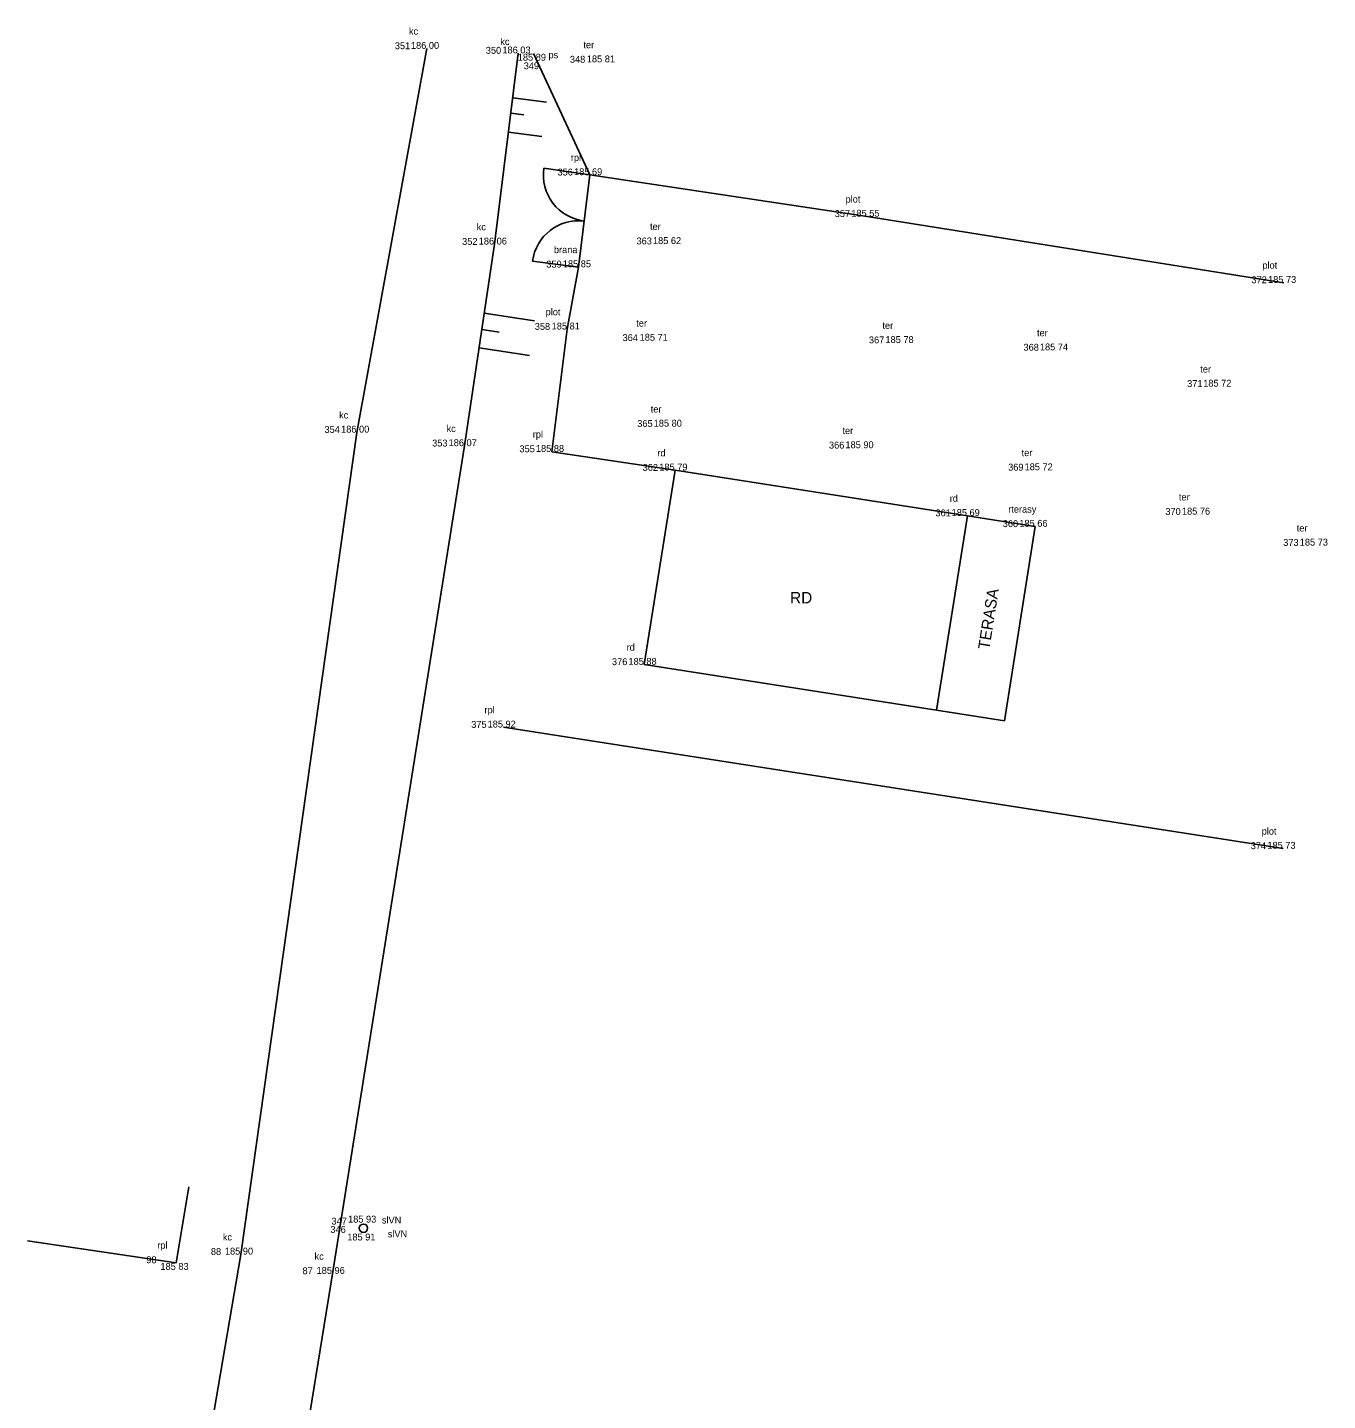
# Model space of a CAD drawing. Extents: x -598527 to -598215, y -1172822 to -1172560.
# Drawn here: x -598511.2 to -598454.6, y -1172660 to -1172600.2 of the extents above; entities that cross this region are included whole.
import ezdxf

# ---------------------------------------------------------------- set-up
doc = ezdxf.new("R2010")
doc.units = 0
for name, color, linetype in [('Body', 7, 'Continuous'), ('Body čísla', 7, 'Continuous'), ('Budovy', 7, 'Continuous'), ('Kody', 7, 'Continuous'), ('PATTERN_CLASS', 7, 'Continuous'), ('Ploty', 7, 'Continuous'), ('Popisy objektu', 7, 'Continuous'), ('Výšky', 7, 'Continuous')]:
    doc.layers.add(name, color=color, linetype=linetype)

msp = doc.modelspace()

# ---------------------------------------------------------------- linework, layer by layer
at = {"layer": 'Body'}
for p, q in [((-598493.82, -1172601.11), (-598493.82, -1172601.11)), ((-598489.84, -1172601.31), (-598489.84, -1172601.31)), ((-598489.17, -1172601.32), (-598489.17, -1172601.32)), ((-598486.18, -1172601.7), (-598486.18, -1172601.7)), ((-598486.72, -1172606.61), (-598486.72, -1172606.61)), ((-598474.65, -1172608.42), (-598474.65, -1172608.42)), ((-598490.87, -1172609.63), (-598490.87, -1172609.63)), ((-598483.28, -1172609.61), (-598483.28, -1172609.61)), ((-598487.21, -1172610.62), (-598487.21, -1172610.62)), ((-598456.5, -1172611.3), (-598456.5, -1172611.3)), ((-598487.71, -1172613.33), (-598487.71, -1172613.33)), ((-598483.88, -1172613.82), (-598483.88, -1172613.82)), ((-598473.16, -1172613.92), (-598473.16, -1172613.92)), ((-598466.43, -1172614.24), (-598466.43, -1172614.24)), ((-598459.32, -1172615.82), (-598459.32, -1172615.82)), ((-598483.25, -1172617.56), (-598483.25, -1172617.56)), ((-598496.86, -1172617.82), (-598496.86, -1172617.82)), ((-598492.18, -1172618.41), (-598492.18, -1172618.41)), ((-598488.38, -1172618.66), (-598488.38, -1172618.66)), ((-598474.9, -1172618.5), (-598474.9, -1172618.5)), ((-598483.01, -1172619.47), (-598483.01, -1172619.47)), ((-598467.1, -1172619.46), (-598467.1, -1172619.46)), ((-598470.28, -1172621.45), (-598470.28, -1172621.45)), ((-598460.25, -1172621.39), (-598460.25, -1172621.39)), ((-598467.33, -1172621.92), (-598467.33, -1172621.92)), ((-598455.12, -1172622.74), (-598455.12, -1172622.74)), ((-598484.35, -1172627.93), (-598484.35, -1172627.93)), ((-598490.48, -1172630.66), (-598490.48, -1172630.66)), ((-598456.53, -1172635.94), (-598456.53, -1172635.94)), ((-598496.61, -1172652.65), (-598496.61, -1172652.65)), ((-598496.56, -1172652.29), (-598496.56, -1172652.29)), ((-598504.73, -1172653.97), (-598504.73, -1172653.97)), ((-598501.92, -1172653.61), (-598501.92, -1172653.61)), ((-598497.93, -1172654.45), (-598497.93, -1172654.45))]:
    msp.add_line(p, q, dxfattribs=at)
at = {"layer": 'Budovy'}
for p, q in [((-598471.62, -1172629.91), (-598470.28, -1172621.45)), ((-598470.28, -1172621.45), (-598467.33, -1172621.92)), ((-598468.67, -1172630.38), (-598467.33, -1172621.92)), ((-598471.62, -1172629.91), (-598468.67, -1172630.38))]:
    msp.add_line(p, q, dxfattribs=at)
for points in [[(-598470.28, -1172621.45), (-598483.01, -1172619.47), (-598484.35, -1172627.93)], [(-598471.62, -1172629.91), (-598484.35, -1172627.93)]]:
    msp.add_lwpolyline(points, dxfattribs=at)
at = {"layer": 'PATTERN_CLASS'}
for p, q in [((-598489.17, -1172601.32), (-598486.72, -1172606.61)), ((-598490.08, -1172603.251), (-598488.601, -1172603.435)), ((-598490.163, -1172603.915), (-598489.594, -1172603.986)), ((-598490.266, -1172604.753), (-598488.808, -1172604.933)), ((-598491.318, -1172612.634), (-598489.135, -1172612.96)), ((-598491.424, -1172613.343), (-598490.663, -1172613.457)), ((-598491.543, -1172614.137), (-598489.348, -1172614.465))]:
    msp.add_line(p, q, dxfattribs=at)
for points in [[(-598493.82, -1172601.11), (-598496.86, -1172617.82), (-598501.92, -1172653.61), (-598505.54, -1172674.85)], [(-598492.58, -1172680.02), (-598497.74, -1172678.52), (-598500.61, -1172676.78), (-598500.8, -1172674.68), (-598499.89, -1172667.42), (-598499.27, -1172662.77), (-598497.93, -1172654.45), (-598492.18, -1172618.41), (-598490.87, -1172609.63), (-598489.84, -1172601.31)]]:
    msp.add_lwpolyline(points, dxfattribs=at)
msp.add_circle((-598496.579, -1172652.471), 0.182, dxfattribs=at)
at = {"layer": 'Ploty'}
for p, q in [((-598486.72, -1172606.61), (-598488.719, -1172606.319)), ((-598487.21, -1172610.62), (-598489.214, -1172610.367)), ((-598488.38, -1172618.66), (-598483.01, -1172619.47)), ((-598490.48, -1172630.66), (-598456.53, -1172635.94)), ((-598504.73, -1172653.97), (-598504.183, -1172650.663)), ((-598504.73, -1172653.97), (-598511.208, -1172653.019))]:
    msp.add_line(p, q, dxfattribs=at)
for points in [[(-598487.21, -1172610.62), (-598486.72, -1172606.61)], [(-598486.72, -1172606.61), (-598474.65, -1172608.42), (-598456.5, -1172611.3)], [(-598488.38, -1172618.66), (-598487.71, -1172613.33), (-598487.212, -1172610.628)]]:
    msp.add_lwpolyline(points, dxfattribs=at)
for centre, start, end in [((-598486.72, -1172606.61), 171.72419, 263.03331), ((-598487.21, -1172610.62), 83.03331, 172.79038)]:
    msp.add_arc(centre, 2.02, start, end, dxfattribs=at)

# ---------------------------------------------------------------- texts
at = {"layer": 'Body čísla'}
for s, p in [('351', (-598495.211, -1172601.133)), ('350', (-598491.25, -1172601.333)), ('348', (-598487.588, -1172601.723)), ('349', (-598489.599, -1172602.006)), ('356', (-598488.127, -1172606.633)), ('357', (-598476.058, -1172608.443)), ('352', (-598492.281, -1172609.653)), ('363', (-598484.687, -1172609.633)), ('359', (-598488.616, -1172610.643)), ('372', (-598457.911, -1172611.323)), ('358', (-598489.118, -1172613.353)), ('364', (-598485.294, -1172613.843)), ('367', (-598474.568, -1172613.943)), ('368', (-598467.838, -1172614.263)), ('371', (-598460.711, -1172615.843)), ('354', (-598498.274, -1172617.843)), ('365', (-598484.655, -1172617.583)), ('353', (-598493.587, -1172618.433)), ('355', (-598489.785, -1172618.683)), ('366', (-598476.307, -1172618.523)), ('362', (-598484.421, -1172619.493)), ('369', (-598468.506, -1172619.483)), ('361', (-598471.671, -1172621.473)), ('370', (-598461.66, -1172621.413)), ('360', (-598468.74, -1172621.943)), ('373', (-598456.527, -1172622.763)), ('376', (-598485.757, -1172627.953)), ('375', (-598491.885, -1172630.683)), ('374', (-598457.944, -1172635.963)), ('347', (-598497.968, -1172652.313)), ('346', (-598498.017, -1172652.673)), ('88', (-598503.221, -1172653.633)), ('98', (-598506.031, -1172653.993)), ('87', (-598499.231, -1172654.473))]:
    msp.add_text(s, height=0.3, dxfattribs=at).set_placement(p)
at = {"layer": 'Kody'}
for s, p in [('kc', (-598494.598, -1172600.503)), ('kc', (-598490.618, -1172600.955)), ('ter', (-598486.999, -1172601.093)), ('ps', (-598488.519, -1172601.532)), ('rpl', (-598487.546, -1172606.003)), ('plot', (-598475.585, -1172607.813)), ('kc', (-598491.648, -1172609.023)), ('ter', (-598484.099, -1172609.003)), ('brana', (-598488.285, -1172610.013)), ('plot', (-598457.435, -1172610.693)), ('plot', (-598488.645, -1172612.723)), ('ter', (-598484.699, -1172613.213)), ('ter', (-598473.979, -1172613.313)), ('ter', (-598467.249, -1172613.633)), ('ter', (-598460.139, -1172615.213)), ('kc', (-598497.638, -1172617.213)), ('ter', (-598484.069, -1172616.953)), ('kc', (-598492.958, -1172617.803)), ('rpl', (-598489.206, -1172618.053)), ('ter', (-598475.719, -1172617.893)), ('rd', (-598483.779, -1172618.863)), ('ter', (-598467.919, -1172618.853)), ('rd', (-598471.049, -1172620.843)), ('ter', (-598461.069, -1172620.783)), ('rterasy', (-598468.501, -1172621.313)), ('ter', (-598455.939, -1172622.133)), ('rd', (-598485.119, -1172627.323)), ('rpl', (-598491.306, -1172630.053)), ('plot', (-598457.465, -1172635.333)), ('slVN', (-598495.776, -1172652.264)), ('kc', (-598502.698, -1172653.003)), ('rpl', (-598505.556, -1172653.363)), ('kc', (-598498.708, -1172653.843))]:
    msp.add_text(s, height=0.3, dxfattribs=at).set_placement(p)
at = {"layer": 'PATTERN_CLASS'}
msp.add_text('slVN', height=0.3, dxfattribs=at).set_placement((-598495.518, -1172652.869))
at = {"layer": 'Popisy objektu'}
msp.add_text('RD', height=0.5, dxfattribs=at).set_placement((-598478.001, -1172625.266))
msp.add_text('TERASA', height=0.5, rotation=80.99955, dxfattribs=at).set_placement((-598469.326, -1172627.302))
at = {"layer": 'Výšky'}
for s, p in [('186 00', (-598494.51, -1172601.118)), ('186 03', (-598490.527, -1172601.318)), ('185 89', (-598489.857, -1172601.634)), ('185 81', (-598486.851, -1172601.708)), ('185 69', (-598487.407, -1172606.618)), ('185 55', (-598475.336, -1172608.428)), ('186 06', (-598491.558, -1172609.638)), ('185 62', (-598483.971, -1172609.618)), ('185 85', (-598487.896, -1172610.628)), ('185 73', (-598457.187, -1172611.308)), ('185 81', (-598488.381, -1172613.338)), ('185 71', (-598484.551, -1172613.828)), ('185 78', (-598473.848, -1172613.928)), ('185 74', (-598467.124, -1172614.248)), ('185 72', (-598460.011, -1172615.828)), ('186 00', (-598497.55, -1172617.828)), ('185 80', (-598483.94, -1172617.568)), ('186 07', (-598492.869, -1172618.418)), ('185 88', (-598489.068, -1172618.668)), ('185 90', (-598475.59, -1172618.508)), ('185 79', (-598483.697, -1172619.478)), ('185 72', (-598467.791, -1172619.468)), ('185 69', (-598470.967, -1172621.458)), ('185 76', (-598460.938, -1172621.398)), ('185 66', (-598468.018, -1172621.928)), ('185 73', (-598455.807, -1172622.748)), ('185 88', (-598485.038, -1172627.938)), ('185 92', (-598491.171, -1172630.668)), ('185 73', (-598457.217, -1172635.948)), ('185 93', (-598497.247, -1172652.224)), ('185 91', (-598497.281, -1172653.003)), ('185 90', (-598502.61, -1172653.618)), ('185 83', (-598505.417, -1172654.282)), ('185 96', (-598498.618, -1172654.458))]:
    msp.add_text(s, height=0.3, dxfattribs=at).set_placement(p)

doc.saveas('drawing.dxf')
